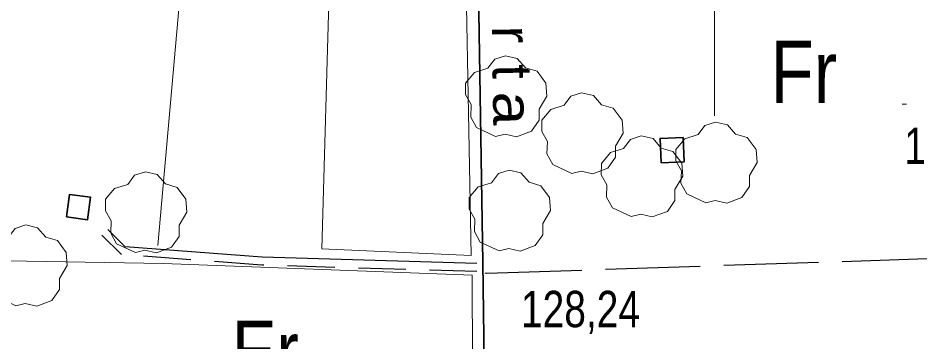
# Model space of a CAD drawing. Extents: x 483847 to 488453, y 4383581 to 4386795.
# Drawn here: x 486832.5 to 487049.4, y 4384420.5 to 4384498.5 of the extents above; entities that cross this region are included whole.
import ezdxf
from ezdxf.enums import TextEntityAlignment as Align

# ---------------------------------------------------------------- set-up
doc = ezdxf.new("R2010")
doc.units = 0
doc.header["$LTSCALE"] = 3.8
doc.linetypes.add('LONG_DASHED', pattern=[7.5, 6, -1.5])
doc.linetypes.add('MEDIUM_DASHED', pattern=[4.5, 3, -1.5])
for name, color, linetype, lineweight in [('1', 7, 'Continuous', 13), ('25', 7, 'LONG_DASHED', 25), ('27', 7, 'Continuous', 25), ('29', 7, 'Continuous', 13), ('38', 7, 'Continuous', 25), ('47', 7, 'Continuous', 35), ('51', 7, 'Continuous', 13), ('6', 7, 'Continuous', 35), ('7', 7, 'Continuous', 13)]:
    doc.layers.add(name, color=color, linetype=linetype, lineweight=lineweight)
doc.layers.add('31', color=7, linetype='Continuous')
doc.layers.add('5', color=7, linetype='Continuous')

msp = doc.modelspace()

# ---------------------------------------------------------------- linework, layer by layer
at = {"layer": '1'}
msp.add_line((487000, 4384525), (487000, 4384475), dxfattribs=at)
at = {"layer": '25'}
msp.add_line((486945.29, 4384437.11), (487144.77, 4384443.7), dxfattribs=at)
at = {"layer": '27'}
msp.add_spline([(486459.96, 4384385.16), (486471.27, 4384378.47), (486473.92, 4384375.28), (486475.39, 4384367.53), (486474.06, 4384364.1), (486468.58, 4384332.36), (486456.37, 4384281.06), (486450.57, 4384253.61), (486437.24, 4384218.91), (486433.21, 4384189.18), (486433.99, 4384185.86), (486436.3, 4384184.33), (486436.97, 4384184.32), (486441.1, 4384184.71), (486447.44, 4384187.32), (486451.82, 4384188.91), (486456.5, 4384190.87), (486459.83, 4384192.92), (486472.99, 4384200.46), (486476.65, 4384203.94), (486479.61, 4384206.22), (486488.62, 4384212.32), (486496.68, 4384219.48), (486502, 4384224.06), (486511.41, 4384231.95), (486539.46, 4384262.46), (486556.14, 4384273.86), (486561.61, 4384278.73), (486564.81, 4384282.06), (486575.24, 4384313.88), (486592.54, 4384347.7), (486603.35, 4384384.68), (486618.29, 4384417.11), (486623.74, 4384425.81), (486629.81, 4384440.88), (486633.7, 4384450.43), (486641.19, 4384465.26), (486647.57, 4384470.57), (486651.57, 4384471.86), (486660.8, 4384471.88), (486687.53, 4384468.12), (486716.08, 4384460.28), (486726.32, 4384457.36), (486741.64, 4384452.94), (486747.02, 4384451.28), (486753.15, 4384449.77), (486767.51, 4384446.79), (486778.5, 4384443.85), (486779.56, 4384439.11), (486777.41, 4384419.93), (486778.13, 4384412.87), (486779.55, 4384406.62), (486783.55, 4384398.31), (486789.34, 4384388.7), (486794.95, 4384381.79), (486806.53, 4384368.27), (486812.52, 4384362.18), (486821.5, 4384354.85), (486839.86, 4384348.2), (486856.39, 4384344.37), (486864.63, 4384343.12), (486886.87, 4384340.33), (486895.94, 4384339.52), (486904.04, 4384339.11), (486909.51, 4384338.95), (486913.63, 4384337.99), (486915.08, 4384334.37), (486915.66, 4384328.28), (486915.43, 4384322.74), (486912.42, 4384321.8), (486907.78, 4384322.62), (486895.36, 4384325.35), (486888.93, 4384326.49), (486882.24, 4384325.99), (486876.01, 4384320.37), (486872.23, 4384313.15), (486873.79, 4384307.2), (486881.33, 4384304.54), (486889.2, 4384303.6), (486900.97, 4384303.06), (486911.02, 4384302.54), (486921.15, 4384302.39), (486925.48, 4384301.06), (486928.7, 4384295.53), (486929.06, 4384289.07), (486922.67, 4384283.16), (486903.92, 4384283.43), (486890.73, 4384279.42), (486884.7, 4384267.35), (486876.54, 4384242.48), (486874.52, 4384232.45)], degree=3, dxfattribs=at)
at = {"layer": '29'}
for points in [[(486947.34, 4384470.03), (486942.8, 4384472.15), (486941.39, 4384474.69), (486941.49, 4384477.67), (486940.12, 4384480.08), (486940.16, 4384482.83), (486942.32, 4384485.43), (486945.51, 4384486.43), (486947.16, 4384488.62), (486949.73, 4384489.45), (486952.59, 4384488.8), (486954.54, 4384486.53), (486957.35, 4384485.71), (486959.48, 4384482.86), (486959.72, 4384479.73), (486957.84, 4384476.58), (486957.84, 4384473.9), (486956.02, 4384471.29), (486952.4, 4384469.95), (486949.63, 4384470.58)], [(486965.67, 4384461.13), (486961.13, 4384463.25), (486959.72, 4384465.79), (486959.82, 4384468.77), (486958.45, 4384471.18), (486958.49, 4384473.93), (486960.65, 4384476.53), (486963.84, 4384477.53), (486965.49, 4384479.72), (486968.06, 4384480.55), (486970.92, 4384479.9), (486972.87, 4384477.63), (486975.68, 4384476.81), (486977.81, 4384473.96), (486978.05, 4384470.83), (486976.17, 4384467.68), (486976.17, 4384465), (486974.35, 4384462.39), (486970.73, 4384461.05), (486967.96, 4384461.68)], [(486997.91, 4384454.07), (486993.37, 4384456.19), (486991.96, 4384458.73), (486992.06, 4384461.71), (486990.69, 4384464.12), (486990.73, 4384466.87), (486992.89, 4384469.47), (486996.08, 4384470.47), (486997.73, 4384472.66), (487000.3, 4384473.49), (487003.16, 4384472.84), (487005.11, 4384470.57), (487007.92, 4384469.75), (487010.05, 4384466.9), (487010.29, 4384463.77), (487008.41, 4384460.62), (487008.41, 4384457.94), (487006.59, 4384455.33), (487002.97, 4384453.99), (487000.2, 4384454.62)], [(486980, 4384450.72), (486975.46, 4384452.84), (486974.05, 4384455.38), (486974.15, 4384458.36), (486972.78, 4384460.77), (486972.82, 4384463.52), (486974.98, 4384466.12), (486978.17, 4384467.12), (486979.82, 4384469.31), (486982.39, 4384470.14), (486985.25, 4384469.49), (486987.2, 4384467.22), (486990.01, 4384466.4), (486992.14, 4384463.55), (486992.38, 4384460.42), (486990.5, 4384457.27), (486990.5, 4384454.59), (486988.68, 4384451.98), (486985.06, 4384450.64), (486982.29, 4384451.27)], [(486948.22, 4384442.48), (486943.68, 4384444.6), (486942.27, 4384447.14), (486942.37, 4384450.12), (486941, 4384452.53), (486941.04, 4384455.28), (486943.2, 4384457.88), (486946.39, 4384458.88), (486948.04, 4384461.07), (486950.61, 4384461.9), (486953.47, 4384461.25), (486955.42, 4384458.98), (486958.23, 4384458.16), (486960.36, 4384455.31), (486960.6, 4384452.18), (486958.72, 4384449.03), (486958.72, 4384446.35), (486956.9, 4384443.74), (486953.28, 4384442.4), (486950.51, 4384443.03)], [(486860.72, 4384442.08), (486856.18, 4384444.2), (486854.77, 4384446.74), (486854.87, 4384449.72), (486853.5, 4384452.13), (486853.54, 4384454.88), (486855.7, 4384457.48), (486858.89, 4384458.48), (486860.54, 4384460.67), (486863.11, 4384461.5), (486865.97, 4384460.85), (486867.92, 4384458.58), (486870.73, 4384457.76), (486872.86, 4384454.91), (486873.1, 4384451.78), (486871.22, 4384448.63), (486871.22, 4384445.95), (486869.4, 4384443.34), (486865.78, 4384442), (486863.01, 4384442.63)], [(486831.95, 4384429.28), (486827.41, 4384431.4), (486826, 4384433.94), (486826.1, 4384436.92), (486824.73, 4384439.33), (486824.77, 4384442.08), (486826.93, 4384444.68), (486830.12, 4384445.68), (486831.77, 4384447.87), (486834.34, 4384448.7), (486837.2, 4384448.05), (486839.15, 4384445.78), (486841.96, 4384444.96), (486844.09, 4384442.11), (486844.33, 4384438.98), (486842.45, 4384435.83), (486842.45, 4384433.15), (486840.63, 4384430.54), (486837.01, 4384429.2), (486834.24, 4384429.83)]]:
    msp.add_lwpolyline(points, close=True, dxfattribs=at)
at = {"layer": '38'}
msp.add_lwpolyline([(486942.84, 4384439.45), (486891.2, 4384440.99), (486858.22, 4384443.48), (486854.06, 4384447.61)], dxfattribs=at)
at = {"layer": '38', "linetype": 'MEDIUM_DASHED'}
msp.add_lwpolyline([(486942.87, 4384437.48), (486891.1, 4384439.03), (486857.35, 4384441.58), (486852.68, 4384446.22)], dxfattribs=at)
at = {"layer": '47'}
for points in [[(486992.5, 4384469.75), (486992.72, 4384463.89), (486987.16, 4384463.68), (486986.94, 4384469.54)], [(486844.11, 4384450.64), (486849.19, 4384449.93), (486849.95, 4384455.36), (486844.87, 4384456.07)]]:
    msp.add_lwpolyline(points, close=True, dxfattribs=at)
at = {"layer": '51'}
msp.add_line((486941.75, 4384436.64), (486941.94, 4384345.09), dxfattribs=at)
for points in [[(486866.14, 4384443.8), (486872.51, 4384516.12), (486880.12, 4384628.64), (486938.46, 4384677.85), (486939.08, 4384584.95), (486939.63, 4384539.99), (486941.45, 4384441.37), (486905.6, 4384442.93), (486908.37, 4384541.94), (486909.95, 4384594.67)], [(486777.94, 4384440.94), (486867.51, 4384439.43), (486941.75, 4384436.64)]]:
    msp.add_lwpolyline(points, dxfattribs=at)
at = {"layer": '6'}
msp.add_lwpolyline([(486945.56, 4384310.48), (486944.94, 4384355.68), (486944.63, 4384415.82), (486944.32, 4384439.71), (486942.16, 4384575.23), (486941.95, 4384690.43)], dxfattribs=at)
at = {"layer": '7'}
for p, q in [((487045.17, 4384477.77), (487046.17, 4384477.77)), ((486944.79, 4384437.11), (486945.79, 4384437.11))]:
    msp.add_line(p, q, dxfattribs=at)

# ---------------------------------------------------------------- texts
at = {"layer": '31'}
for s, width, p in [('Fr', 0.85, (487021.51, 4384478.08)), ('Er', 0.8, (486891.97, 4384410.71))]:
    msp.add_text(s, height=15, dxfattribs=dict(at, width=width)).set_placement(p, align=Align.CENTER)
at = {"layer": '5'}
for s, rotation, p in [('r', 271.089, (486946.48, 4384494.44)), ('t', 270.981, (486946.63, 4384485.56))]:
    msp.add_text(s, height=9.49, rotation=rotation, dxfattribs=at).set_placement(p, align=Align.CENTER)
at = {"layer": '5', "width": 1.15}
msp.add_text('a', height=9.49, rotation=270.981, dxfattribs=at).set_placement((486946.78, 4384476.7), align=Align.CENTER)
at = {"layer": '7', "width": 0.8}
for s, p in [('128,49', (487045.67, 4384463.4)), ('128,24', (486953.47, 4384424.1))]:
    msp.add_text(s, height=8.75, dxfattribs=at).set_placement(p)

doc.saveas('drawing.dxf')
